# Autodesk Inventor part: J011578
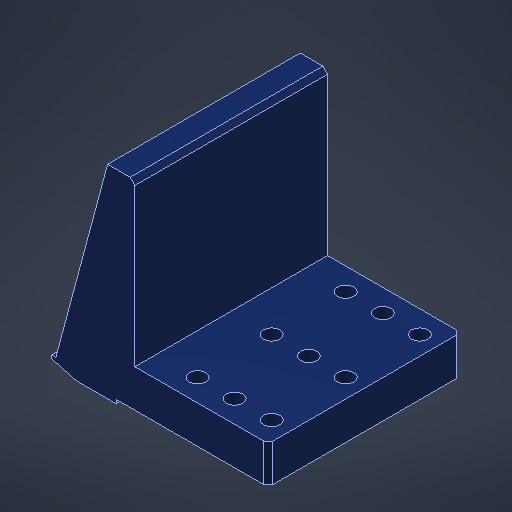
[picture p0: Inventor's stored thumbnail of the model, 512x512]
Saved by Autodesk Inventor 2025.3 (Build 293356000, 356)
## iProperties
RuleStatus: InUse
Created: 2026-02
Project: COMMON
Material: ALUMINUM, 6061-T651
Catalog Web Link: https://www.janelia.org/
Vendor: HHMI: JRC - JET
Document SubType Name: Modeling
Designer: sohna
Density: 2.7 g/cm^3
Appearance: RAL5002_Ultramarine_blue
Part Number: J011578
Description: VENT GONIO TO XY BRKT
AfterDocSave0: file://Part Number Cleaner
LAB/DEPT: COMMON
REQUESTING SCIENTIST: COMMON
SURFACE ROUGHNESS: 63 Ra
DESIGN DEPARTMENT: HHMI: JRC - ID&F
SPECIAL FINISH: ANODIZE PER MIL-A-8625F, TYPE II, CLASS 2 (BLACK)
ALTERED ITEM PART NUMBER: N/A
ALTERED ITEM VENDOR: N/A
ALTERED ITEM DESCRIPTION: N/A
Title: Standard
Author: sohna
Revision Number: -
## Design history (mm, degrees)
sketch "Sketch1"
  geometry: L1 (0, 189.889)-(0, -64.245) reference; L2 (-143.617, 0)-(99.769, 0) reference; L3 (65, 0)-(-65, 0); L4 (-65, 0)-(-65, 25.4); L5 (-65, 25.4)-(65, 25.4); L6 (65, 25.4)-(65, 0); L7 (-105.737, 3.866)-(-65.62, 153.584); L8 (-65.62, 153.584)-(-65, 153.584); L9 (-65, 153.584)-(-65, 25.4); L10 (-105.737, 3.866)-(-108.19, 4.523); L11 (-108.19, 4.523)-(-108.847, 2.07); L12 (-108.847, 2.07)-(-91.643, -2.54); L13 (-65, 0)-(-65, -27.94); L14 (-65, -2.54)-(-65, 0); L15 (-65, 0)-(-65, 0); L16 (-65, 153.584)-(-52.3, 153.584); L17 (-52.3, 153.584)-(-52.3, 25.4); L18 (-52.3, 25.4)-(-65, 25.4); L19 (-65, 25.4)-(-65, 153.584); L20 (-65, -2.54)-(-91.643, -2.54); L21 (-70.724, 134.534)-(-52.3, 134.534); 3 further points
  constraints: 39 end point, 8 perpendicular, 6 point on line, 5 parallel, 3 horizontal, 1 collinear, 1 vertical, 1 other
  dimensions: "d0" = 130 distance of L4.end L5.end; "d1" = 25.4 distance of L5.end L3.start; "d2" = 40.73652 distance from line of L7.start L4; "d4" = 155 distance of L7.start L7.end; "d5" = 75 deg angle of L2 L7; "d9" = 2.54 distance between parallel lines of L12 L10; "d10" = 2.54 distance between parallel lines of L7 L11; "d21" = 12.7 distance of L8.end L16.end; "d46" = 3.86588 distance from line of L7.start L2; "d47" = 2.54 distance between parallel lines of L20 L2; "d48" = 19.05 distance between parallel lines of L21 L16
extrude "Extrusion1" new body sketch "Sketch1" stored distance "d19" = 130; taper "d20" = 0 deg
sketch "Sketch2"
  geometry: L1 (65, 205.886)-(65, -42.472) reference; L2 (0, 0)-(130, 0) reference; L3 (15, 27.5)-(115, 27.5); L4 (115, 27.5)-(115, 127.5); L5 (115, 127.5)-(15, 127.5); L6 (15, 127.5)-(15, 27.5); L7 (15, 27.5)-(115, 127.5); L8 (115, 27.5)-(15, 127.5); 6 further points
  constraints: 12 end point, 4 coincident, 2 midpoint, 2 parallel, 2 perpendicular, 1 horizontal, 1 point on line
  dimensions: "d22" = 27.5 distance between parallel lines of L2 L3; "d23" = 100 distance of L3.end L4.end
hole "Hole1" sketch "Sketch2" at (15, 127.5), (15, 27.5), (115, 127.5), (115, 27.5) diameter "d24" = 4.917; stored, may be unused: countersink angle "d28" = 82 deg, drill point angle "d30" = 118 deg; dims "d25" = 11.9888, "d26" = 9.525, "d27" = 6.35, "d29" = 17.0942
sketch "Sketch3"
  geometry: L1 (-12.7, 130)-(-12.7, 0) reference; L2 (-12.7, 130)-(-12.7, 0) reference; L3 (52.3, 156)-(52.3, -26) reference; L4 (152.069, 65)-(-91.317, 65) reference; L5 (77.3, 115)-(27.3, 115); L6 (27.3, 115)-(27.3, 15); L7 (27.3, 15)-(77.3, 15); L8 (77.3, 15)-(77.3, 115); L9 (77.3, 115)-(27.3, 15); L10 (27.3, 115)-(77.3, 15); 10 further points
  constraints: 12 end point, 6 midpoint, 5 coincident, 2 parallel, 1 horizontal, 1 perpendicular
  dimensions: "d31" = 50 distance of L6.end L7.end; "d32" = 100 distance of L7.end L5.start
hole "Hole2" sketch "Sketch3" at (77.3, 15), (52.3, 15), (27.3, 15), (27.3, 65), (52.3, 65), (77.3, 65), (77.3, 115), (52.3, 115), (27.3, 115) diameter "d33" = 6.604; stored, may be unused: countersink angle "d37" = 82 deg, drill point angle "d39" = 118 deg; dims "d34" = 11.9888, "d35" = 10.9982, "d36" = 19.05, "d38" = 17.0942
sketch "Sketch4"
  geometry: L1 (117.3, 130)-(117.3, 0) reference; L2 (117.3, 0)-(0, 0) reference; L3 (0, 130)-(117.3, 130) reference; L4 (90, 0)-(90, 130); C1 r 3.302 at (77.3, 15) reference; 1 further point
  constraints: 2 end point, 2 point on line, 1 perpendicular
  dimensions: "d40" = 12.7 distance from line of L4 C1.centre
extrude "Extrusion2" cut sketch "Sketch4" extent not by distance; stored distance "d41" = 0; taper "d42" = 0 deg
chamfer "Chamfer1" distance "d43" = 3.175; stored, may be unused: second distance "d44" = 3.175, angle "d45" = 45 deg
body "Solid1"
node "Projected Loop1"
